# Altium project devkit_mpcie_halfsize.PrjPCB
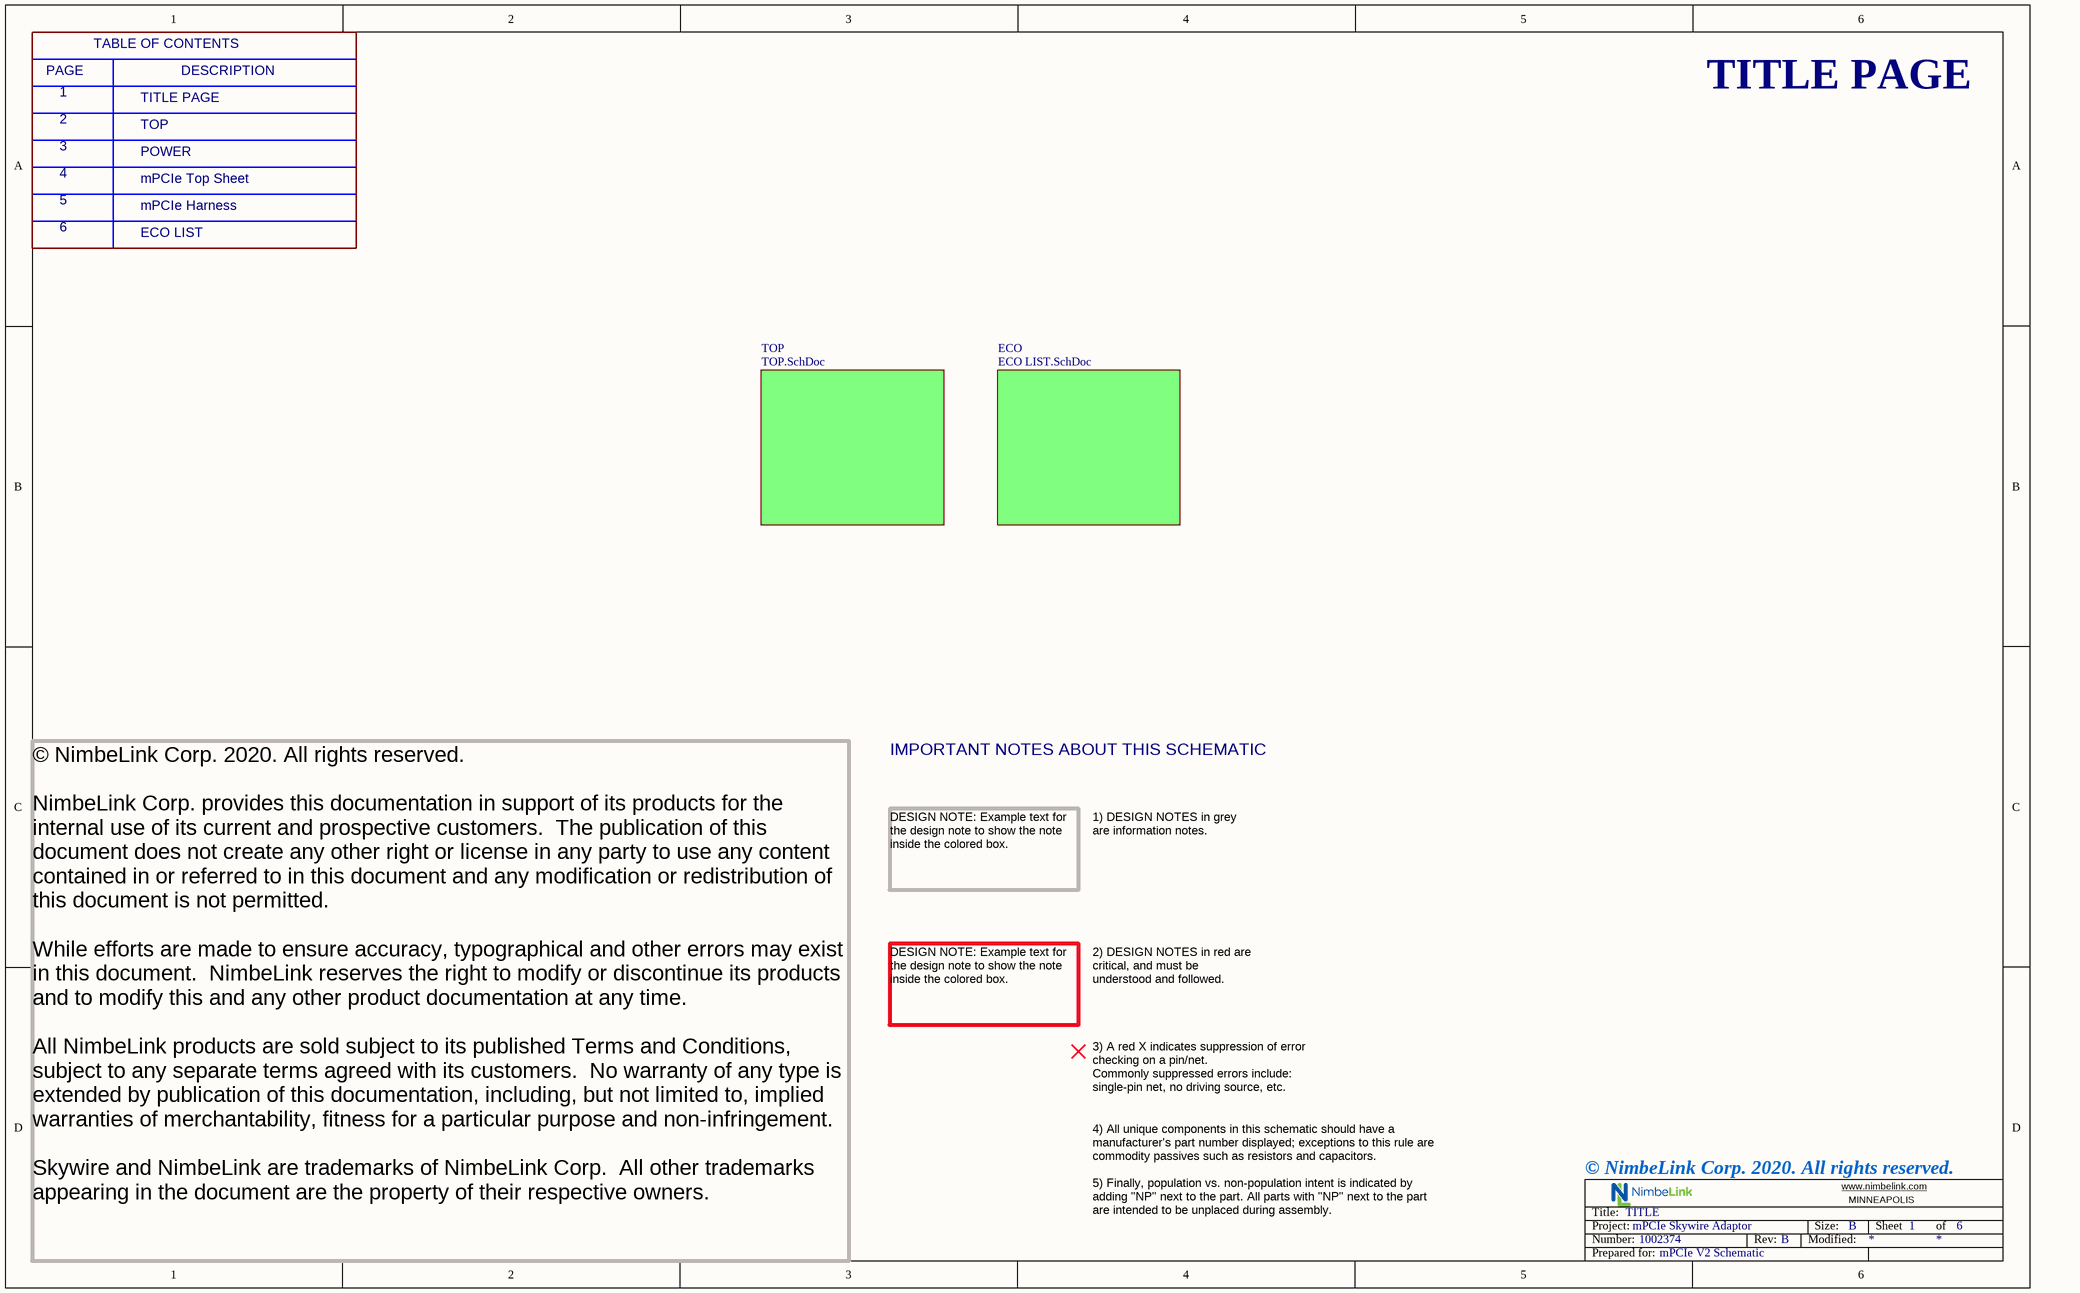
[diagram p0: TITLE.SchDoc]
Template Source URL: http://www.pcisig.com/members/downloads/specifications/pciexpress/PCI_Express_Mini_CEM_12_26Oct07_ncb.pdf; Template Source Revision Date: rev 1.2, Oct 26, 2007; Template Source Organization: Nimbelink; Template Source Name: PCI Express Mini CEM 1.2; Template Family: PCI Express; ProjectTitle: Skywire mPCIe V2 half card; ProjectOrganization: Nimbelink, Corp; NL_VERBOSE_CUST_NAME: mPCIe V2 Schematic; NL_SCH_REV: B; NL_SCH_PN: 1002374; NL_PCBA_REV: B; NL_PCBA_PN: 1002373; NL_PCB_REV: A; NL_PCB_PN: 1002580; NL_BILLING_CODE: mPCIe Skywire Adaptor
6 sheets, 85 parts. Net scope: flat (ports and power ports of the same name join across sheets).
Board file: devkit_mpcie_halfsize.PcbDoc
Sheets:
  TITLE.SchDoc
    TOP = TOP.SchDoc
      Designator = PCI Express Mini_3000X2680_52PIN_Half-Mini-Type H2.schdoc
        U_CON_PCI Express Mini_P1_52PIN = CON_PCI Express Mini_P1_52PIN.SchDoc
      Power = Power.SchDoc
    ECO = ECO LIST.SchDoc

## Sheet TITLE.SchDoc: TITLE
size B; DocumentNumber: 1; SheetNumber: 1; SheetTotal: 6

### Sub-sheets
ECO = ECO LIST.SchDoc: no entries
TOP = TOP.SchDoc: no entries

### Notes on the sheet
- PAGE
- 1
- TABLE OF CONTENTS
- TITLE PAGE
- DESCRIPTION
- 2
- 3
- TOP
- POWER
- 4
- 5
- 6
- mPCIe Top Sheet
- ECO LIST
- mPCIe Harness
- IMPORTANT NOTES ABOUT THIS SCHEMATIC
- DESIGN NOTE: Example text for the design note to show the note inside the colored box.
- 1) DESIGN NOTES in grey are information notes.
- 2) DESIGN NOTES in red are critical, and must be understood and followed.
- 3) A red X indicates suppression of error checking on a pin/net.
  Commonly suppressed errors include: single-pin net, no driving source, etc.
- © NimbeLink Corp. 2020. All rights reserved.
- 4) All unique components in this schematic should have a manufacturer's part number displayed; exceptions to this rule are commodity passives such as resistors and capacitors.
  5) Finally, population vs. non-population intent is indicated by adding "NP" next to the part. All parts with "NP" next to the part are intended to be unplaced during assembly.
- © NimbeLink Corp. 2020. All rights reserved.
  NimbeLink Corp. provides this documentation in support of its products for the internal use of its current and prospective customers.  The publication of this document does not create any other right or license in any party to use any content contained in or referred to in this document and any modification or redistribution of this document is not permitted.
  While efforts are made to ensure accuracy, typographical and other errors may exist in this document.  NimbeLink reserves the right to modify or discontinue its products and to modify this and any other product documentation at any time.
  All NimbeLink products are sold subject to its published Terms and Conditions, subject to any separate terms agreed with its customers.  No warranty of any type is extended by publication of this documentation, including, but not limited to, implied warranties of merchantability, fitness for a particular purpose and non-infringement.
  Skywire and NimbeLink are trademarks of NimbeLink Corp.  All other trademarks appearing in the document are the property of their respective owners.

## Sheet TOP.SchDoc: TOP
size B; DocumentNumber: 2; SheetNumber: 2; SheetTotal: 6
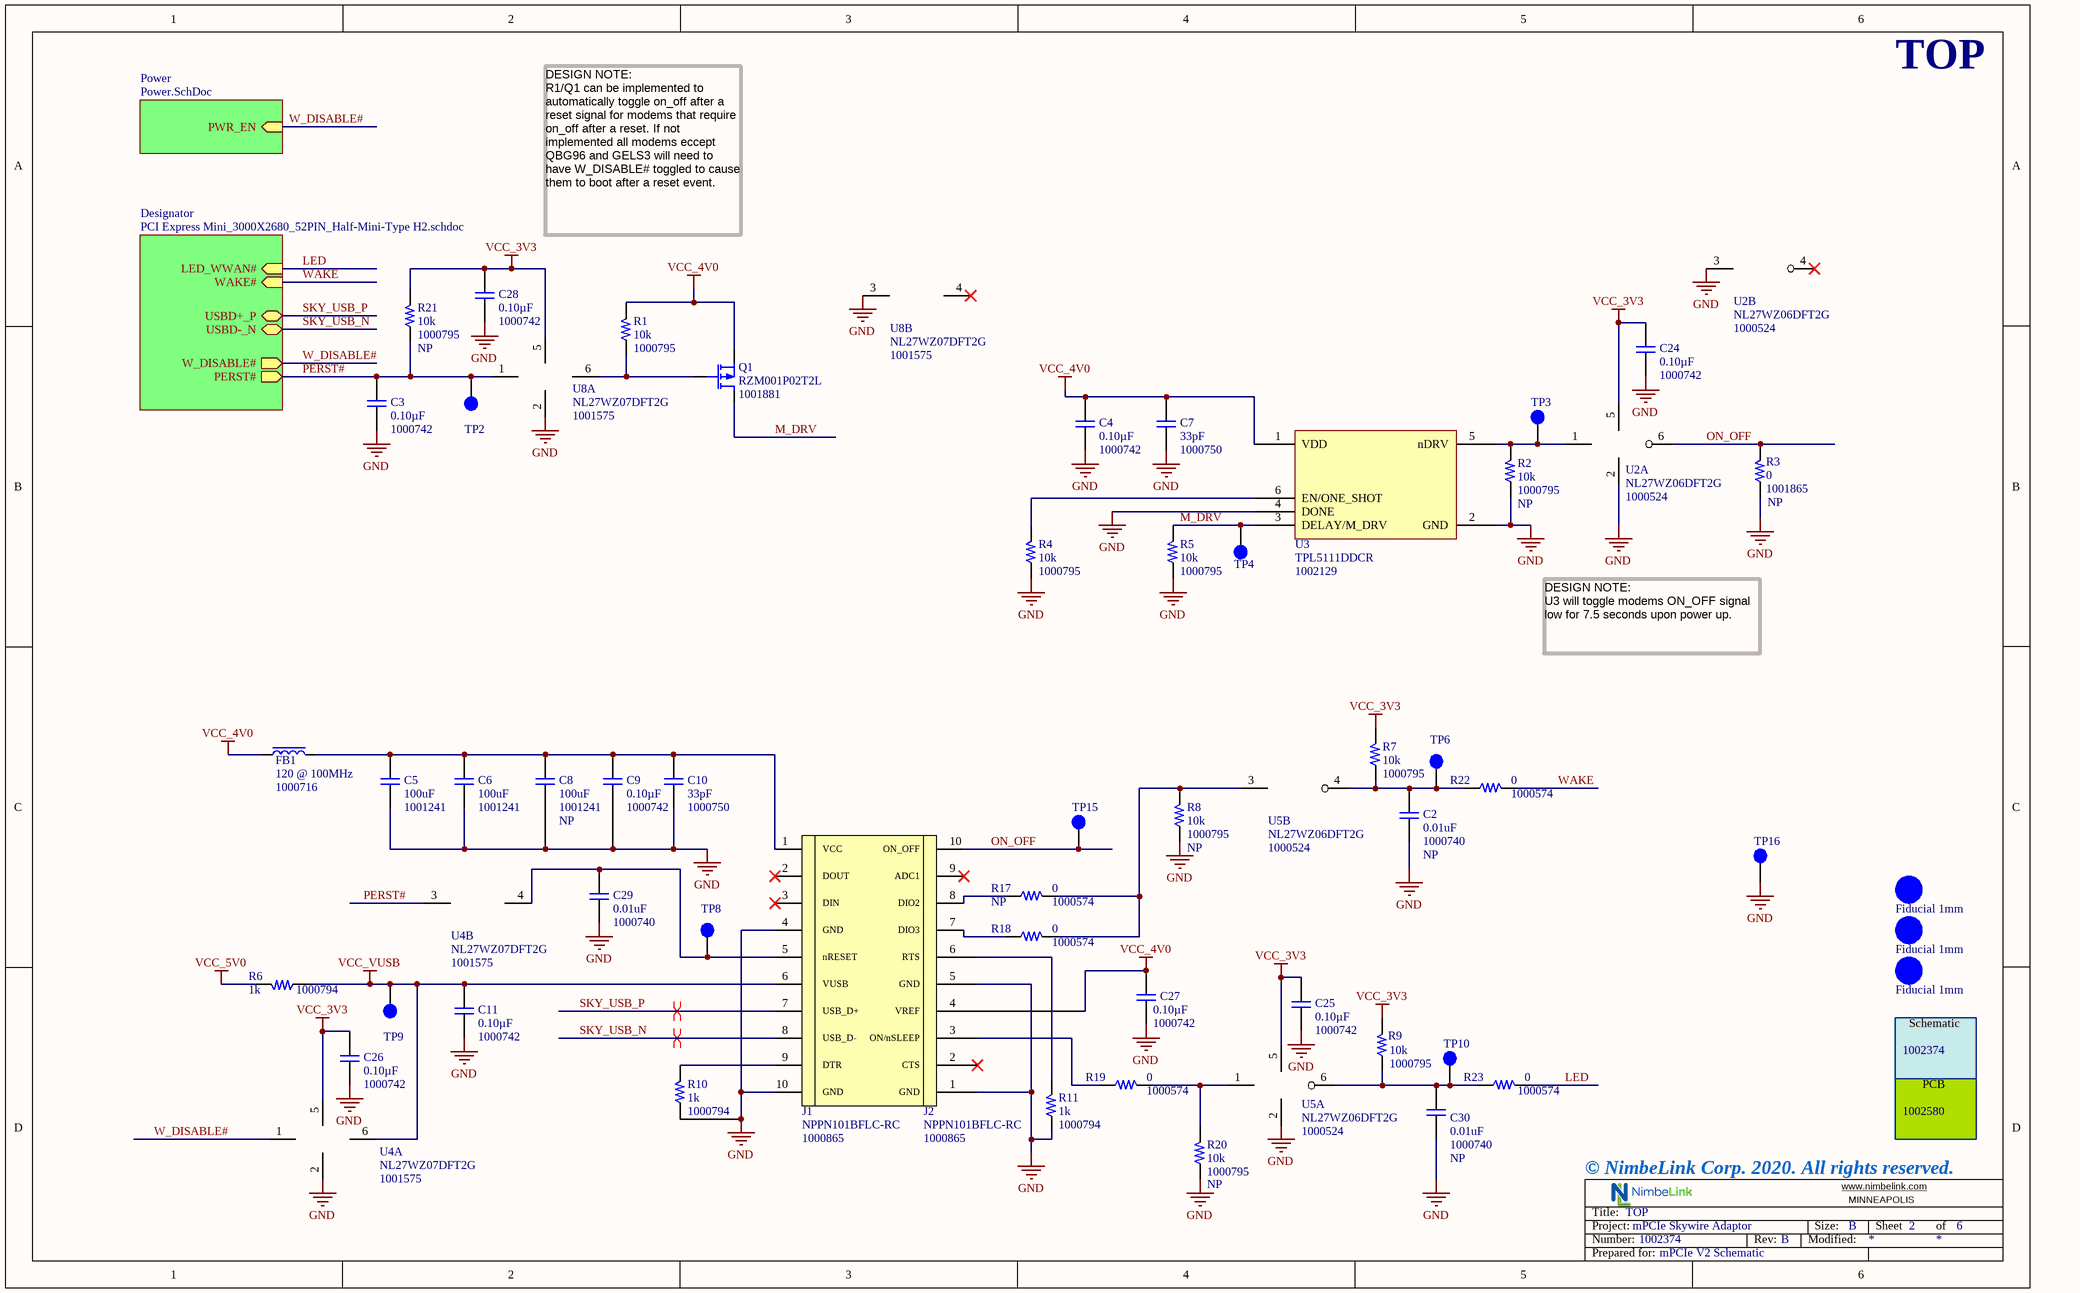
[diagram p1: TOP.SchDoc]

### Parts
C2  Population: NP  Part_Number: 1000740  Capacitance: 0.01uF  [0402]  (hidden comment: CAPACITOR)
C3  Capacitance: 0.10µF  Part_Number: 1000742  [0402]
C4  Capacitance: 0.10µF  Part_Number: 1000742  [0402]
C5  Capacitance: 100uF  [CAPC3225X25N_1210]  (hidden comment: 1001241)
C6  Capacitance: 100uF  [CAPC3225X25N_1210]  (hidden comment: 1001241)
C7  Part_Number: 1000750  Capacitance: 33pF  [0402]  (hidden comment: C, 33 pF, 50V, 5%, C0G/NP0, 0402 CER)
C8  Population: NP  Capacitance: 100uF  [CAPC3225X25N_1210]  (hidden comment: 1001241)
C9  Capacitance: 0.10µF  Part_Number: 1000742  [0402]
C10  Part_Number: 1000750  Capacitance: 33pF  [0402]  (hidden comment: C, 33 pF, 50V, 5%, C0G/NP0, 0402 CER)
C11  Capacitance: 0.10µF  Part_Number: 1000742  [0402]
C24  Capacitance: 0.10µF  Part_Number: 1000742  [0402]
C25  Capacitance: 0.10µF  Part_Number: 1000742  [0402]
C26  Capacitance: 0.10µF  Part_Number: 1000742  [0402]
C27  Capacitance: 0.10µF  Part_Number: 1000742  [0402]
C28  Capacitance: 0.10µF  Part_Number: 1000742  [0402]
C29  Part_Number: 1000740  Capacitance: 0.01uF  [0402]  (hidden comment: CAPACITOR)
C30  Population: NP  Part_Number: 1000740  Capacitance: 0.01uF  [0402]  (hidden comment: CAPACITOR)
FB1  Part_Number: 1000716  Resistance_at_Frequency: 120 @ 100MHz  [0603]  (hidden comment: PE-0603PFB121ST)
Fiducial1  Fiducial 1mm  [Fiducial 1mm]  (no BOM)
Fiducial2  Fiducial 1mm  [Fiducial 1mm]  (no BOM)
Fiducial3  Fiducial 1mm  [Fiducial 1mm]  (no BOM)
J1  1000865  [NPPN101BFLC-RC]
J2  1000865  [NPPN101BFLC-RC]
PCB1  Part_Number: 1002580  (hidden comment: PCB)  (mechanical)
Q1  Manufacturer_Part_Number1: RZM001P02T2L  Part_Number: 1001881  [SOT-723]  (hidden comment: MOSFET_P)
R1  Part_Number: 1000795  Resistance_Ohms: 10k  [0402]  (hidden comment: R, 10K, 1%, 1/16W,  0402)
R2  Population: NP  Part_Number: 1000795  Resistance_Ohms: 10k  [0402]  (hidden comment: R, 10K, 1%, 1/16W,  0402)
R3  Population: NP  Resistance_Ohms: 0  Part_Number: 1001865  [0402]  (hidden comment: RESISTOR)
R4  Part_Number: 1000795  Resistance_Ohms: 10k  [0402]  (hidden comment: R, 10K, 1%, 1/16W,  0402)
R5  Part_Number: 1000795  Resistance_Ohms: 10k  [0402]  (hidden comment: R, 10K, 1%, 1/16W,  0402)
R6  Part_Number: 1000794  Resistance_Ohms: 1k  [0402]  (hidden comment: R, 1K, 1%, 1/16W, 0402)
R7  Part_Number: 1000795  Resistance_Ohms: 10k  [0402]  (hidden comment: R, 10K, 1%, 1/16W,  0402)
R8  Population: NP  Part_Number: 1000795  Resistance_Ohms: 10k  [0402]  (hidden comment: R, 10K, 1%, 1/16W,  0402)
R9  Part_Number: 1000795  Resistance_Ohms: 10k  [0402]  (hidden comment: R, 10K, 1%, 1/16W,  0402)
R10  Part_Number: 1000794  Resistance_Ohms: 1k  [0402]  (hidden comment: R, 1K, 1%, 1/16W, 0402)
R11  Part_Number: 1000794  Resistance_Ohms: 1k  [0402]  (hidden comment: R, 1K, 1%, 1/16W, 0402)
R17  Population: NP  Part_Number: 1000574  [0402]  (hidden comment: 0)
R18  Part_Number: 1000574  [0402]  (hidden comment: 0)
R19  Part_Number: 1000574  [0402]  (hidden comment: 0)
R20  Population: NP  Part_Number: 1000795  Resistance_Ohms: 10k  [0402]  (hidden comment: R, 10K, 1%, 1/16W,  0402)
R21  Population: NP  Part_Number: 1000795  Resistance_Ohms: 10k  [0402]  (hidden comment: R, 10K, 1%, 1/16W,  0402)
R22  Part_Number: 1000574  [0402]  (hidden comment: 0)
R23  Part_Number: 1000574  [0402]  (hidden comment: 0)
SCH1  Part_Number: 1002374  (hidden comment: SCH)  (mechanical)
TP2  Test Point 1mm  [Test_Point 1mm]  (value not drawn)  (no BOM)
TP3  Test Point 1mm  [Test_Point 1mm]  (value not drawn)  (no BOM)
TP4  Test Point 1mm  [Test_Point 1mm]  (value not drawn)  (no BOM)
TP6  Test Point 1mm  [Test_Point 1mm]  (value not drawn)  (no BOM)
TP8  Test Point 1mm  [Test_Point 1mm]  (value not drawn)  (no BOM)
TP9  Test Point 1mm  [Test_Point 1mm]  (value not drawn)  (no BOM)
TP10  Test Point 1mm  [Test_Point 1mm]  (value not drawn)  (no BOM)
TP15  Test Point 1mm  [Test_Point 1mm]  (value not drawn)  (no BOM)
TP16  Test Point 1mm  [Test_Point 1mm]  (value not drawn)  (no BOM)
U2  Part_Number: 1000524  [SOT65P210X110-6N]  (hidden comment: NL27WZ06DFT2G)  (parts A,B of 2)
U3  Manufacturer_Part_Number1: TPL5111DDCR  Part_Number: 1002129  [SOT95P280X110-6N]  (hidden comment: TPL5111)
U4  Part_Number: 1001575  [SOT65P210X110-6N]  (hidden comment: NL27WZ07DFT2G)  (parts A,B of 2)
U5  Part_Number: 1000524  [SOT65P210X110-6N]  (hidden comment: NL27WZ06DFT2G)  (parts A,B of 2)
U8  Part_Number: 1001575  [SOT65P210X110-6N]  (hidden comment: NL27WZ07DFT2G)  (parts A,B of 2)

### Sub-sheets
Designator = PCI Express Mini_3000X2680_52PIN_Half-Mini-Type H2.schdoc: USBD+_P (bidir), USBD-_N (bidir), PERST# (out), WAKE# (in), LED_WWAN# (in), W_DISABLE# (out)
Power = Power.SchDoc: PWR_EN (in)

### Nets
GND: C2.2 C3.2 C4.2 C5.2 C6.2 C7.2 C8.2 C9.2 C10.2 C11.2 C24.2 C25.2 C26.2 C27.2 C28.2 C29.2 C30.2 J1.4 J1.10 J2.1 J2.5 R2.1 R3.1 R4.1 R5.1 R8.1 R10.1 R11.1 R20.1 TP16.1 U2.2(GND) U2.3 U3.2(GND) U3.4(DONE) U4.2(GND) U5.2(GND) U8.2(GND) U8.3
VCC_3V3: C24.1 C25.1 C26.1 C28.1 R7.2 R9.2 R21.2 U2.5(VCC) U4.5(VCC) U5.5(VCC) U8.5(VCC)
VCC_4V0: C4.1 C7.1 C27.1 FB1.1 J2.4 Q1.2(S) R1.2 U3.1(VDD)
VCC_5V0: R6.2
VCC_VUSB: C11.1 J1.6 R6.1 TP9.1 U4.6
LED: R23.2 ; sheet Designator/LED_WWAN#
M_DRV: Q1.3(D) R5.2 TP4.1 U3.3(DELAY/M_DRV)
ON_OFF: J2.10 R3.2 TP15.1 U2.6
PERST#: C3.1 R21.1 TP2.1 U4.3 U8.1 ; sheet Designator/PERST#
SKY_USB_N: J1.8 ; sheet Designator/USBD-_N
SKY_USB_P: J1.7 ; sheet Designator/USBD+_P
W_DISABLE#: U4.1 ; sheet Designator/W_DISABLE#, sheet Power/PWR_EN
WAKE: R22.2 ; sheet Designator/WAKE#
NetC2_1: C2.1 R7.1 R22.1 TP6.1 U5.4
NetC5_1: C5.1 C6.1 C8.1 C9.1 C10.1 FB1.2 J1.1
NetC29_1: C29.1 J1.5 TP8.1 U4.4
NetC30_1: C30.1 R9.1 R23.1 TP10.1 U5.6
NetJ1_9: J1.9 R10.2
NetJ2_3: J2.3 R19.1
NetJ2_6: J2.6 R11.2
NetJ2_7: J2.7 R18.1
NetJ2_8: J2.8 R17.1
NetQ1_1: Q1.1(G) R1.1 U8.6
NetR2_2: R2.2 TP3.1 U2.1 U3.5(nDRV)
NetR4_2: R4.2 U3.6(EN/ONE_SHOT)
NetR8_2: R8.2 R17.2 R18.2 U5.3
NetR19_2: R19.2 R20.2 U5.1

Not connected (* = marked no-connect by the designer): J1 2* 3*; J2 2* 9*; U2 4*; U8 4*

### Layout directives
differential pair: SKY_USB_N, SKY_USB_P

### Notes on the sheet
- TOP
- DESIGN NOTE:
  R1/Q1 can be implemented to automatically toggle on_off after a reset signal for modems that require on_off after a reset. If not implemented all modems eccept QBG96 and GELS3 will need to have W_DISABLE# toggled to cause them to boot after a reset event.
- DESIGN NOTE:
  U3 will toggle modems ON_OFF signal low for 7.5 seconds upon power up.
- (near J1) VCC
- (near J1) DOUT
- (near J1) DIN
- (near J2) ON_OFF
- (near J2) ADC1
- (near J2) DIO2
- (near J1) GND
- (near J1) nRESET
- (near J2) DIO3
- (near J2) RTS
- (near J1) VUSB
- (near J1) USB_D+
- (near J1) USB_D-
- (near J2) ON/nSLEEP
- (near J2) VREF
- (near J2) GND
- (near J1) DTR
- (near J2) CTS
- (near PCB1) © NimbeLink Corp. 2020. All rights reserved.

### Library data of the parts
C2 C29 C30 = 1000740: Capacitor, 0.01 uF, 25V, 5%, X7R, 0402
C3 C4 C9 C11 C24-C28 = 1000742: Capacitor, 0.1 uF, 16V, 10%, X7R, 0402; Manufacturer1: Kemet; Manufacturer_Part_Number1: C0402C104K4RALTU; Item_Phase: Production; Capacitor_Type: Ceramic; Mounting_Type: Surface Mount; Operating_Temperature: -55°C ~ 125°C; Thickness_Max: 0.022" (0.55mm)
C5 C6 C8 = 1001241: Capacitor. 100uF, 10V, 20%, X5R, 1210; Manufacturer1: Taiyo Yuden; Tolerance: +/- 20%; Item_Phase: Production; Capacitor_Type: Ceramic; Mounting_Type: Surface Mount; Operating_Temperature: -55C ~ +85C; Thickness_Max: 0.106 (2.70mm)"
C7 C10 = 1000750: Capacitor, 33 pF, 50V, 5%, C0G/NP0, 0402; Manufacturer1: Kemet; Manufacturer_Part_Number1: C0402C330J5GACTU; Item_Phase: Production; Capacitor_Type: Ceramic; Mounting_Type: Surface Mount; Operating_Temperature: -55°C ~ 125°C; Temperature_Coefficient: C0G, NP0; Thickness_Max: 0.022" (0.55mm)
FB1 = 1000716: Ferrite Bead, 120 ohm @100mHz, 2A, 50mOHM-DC, 0603; Manufacturer_Part_Number1: BLM18PG121SZ1D; Manufacturer1: Murata Electronics North America; Item_Phase: Production; Mounting_Type: Surface Mount; Resistance_DC: 50 mOhm
Fiducial1-Fiducial3 = Fiducial: Population: NP
J1 J2 = 1000865: Connector, Female, 2.00mm, 10x1, SMD, Left Oriented; Manufacturer1: Sullins Connector Solutions; Item_Phase: Production; Connector_Type: Header; Contact_Finish: Gold; Contact_Type: Female Socket; Current_Rating: 2A; Fastening_Type: Push-Pull; Header_Orientation: Vertical; Insertion_Removal_Method: Push In / Pull Out; Mounting_Type: Surface Mount; Number_of_Pins: 10; Number_of_Rows: 1; Operating_Temperature: -40°C ~ 105°C; Pitch: 0.079" (2.00mm); Voltage_Rating: 150V
PCB1 = PCB: PCB Part Number
Q1 = 1001881: Transistor, MOSFET, P-CH, 20V, 0.100A, SOT-723; Manufacturer1: Rohm Semiconductor; Item_Phase: Production; Mounting_Type: Surface Mount; Operating_Temperature: -55°C ~ 150°C; Transistor_Type: PCH - FET
R1 R2 R4 R5 R7-R9 R20 R21 = 1000795: Resistor, 10K, 1%, 1/16W, 0402; Manufacturer1: Bourns Inc; Manufacturer_Part_Number1: CR0402-FX-1002GLF; Item_Phase: Production; Mounting_Type: Surface Mount; Number_of_Terminations: 2; Operating_Temperature: -55°C ~ 155°C; Power: 0.063W, 1/16W; Resistor_Package: 0402 (1005 Metric); Temperature_Coefficient: ±100ppm/°C
R3 = 1001865: Resistor, 0, 1/16W, 0402; Manufacturer1: Bourns Inc; Manufacturer_Part_Number1: CR0402-J/-000GLF; Item_Phase: Production; Mounting_Type: Surface Mount; Number_of_Terminations: 2; Operating_Temperature: -55C ~ 155C; Resistor_Package: 0402 (1005 Metric)
R6 R10 R11 = 1000794: Resistor, 1K, 1%, 1/16W, 0402; Manufacturer1: Bourns Inc; Manufacturer_Part_Number1: CR0402-FX-1001GLF; Item_Phase: Production; Mounting_Type: Surface Mount; Number_of_Terminations: 2; Operating_Temperature: -55°C ~ 155°C; Power: 0.063W, 1/16W; Resistor_Package: 0402 (1005 Metric); Temperature_Coefficient: ±100ppm/°C
R17-R19 R22 R23 = 1000574: Resistor, 0, 1/10W, 0402; Manufacturer1: Panasonic Electronic Components; Manufacturer_Part_Number1: ERJ-2GE0R00X; Item_Phase: Production; Mounting_Type: Surface Mount; Number_of_Terminations: 2; Operating_Temperature: -55°C ~ 155°C; Power: 0.1W, 1/10W; Resistor_Package: 0402 (1005 Metric); Tolerance: Jumper
SCH1 = SCH: Schematic Part Number
TP2-TP4 TP6 TP8-TP10 TP15 TP16 = TP_1mm: TEST POINT, SMD 1mm; Population: NP
U2 U5 = 1000524: IC, Inverter, Dual, Open Drain,1.65-5.5V, SC88; Manufacturer1: ON Semiconductor; Item_Phase: Production; Mounting_Type: Surface Mount; Operating_Temperature: -55°C ~ 125°C; Voltage_Supply_Max: 5.5V; Voltage_Supply_Min: 1.65V
U3 = 1002129: IC, Timer, 0.1-7200s, 1%, 1.8V-5.5V, TSOT-23-6; Manufacturer1: Texas Instruments; Item_Phase: Production; IC_Function: Logic; Mounting_Type: Surface Mount; Operating_Temperature: -40C to +105C; Voltage_Supply_Max: 5.5V; Voltage_Supply_Min: 1.8V; Voltage_Supply_Typical: 3.3V
U4 U8 = 1001575: IC, Buffer, Dual, Open Drain,1.65-5.5V, SC88; Manufacturer1: ON Semiconductor; Item_Phase: Preliminary; IC_Function: Logic; Mounting_Type: Surface Mount; Operating_Temperature: -55°C ~ 125°C; Voltage_Supply_Max: 5.5V; Voltage_Supply_Min: 1.65V

## Sheet PCI Express Mini_3000X2680_52PIN_Half-Mini-Type H2.schdoc: PCI Express H2 Top Sheet
size B; DocumentNumber: 4; Revision: 3; SheetNumber: 4; SheetTotal: 6; Item: 20027; ItemRevision: 3
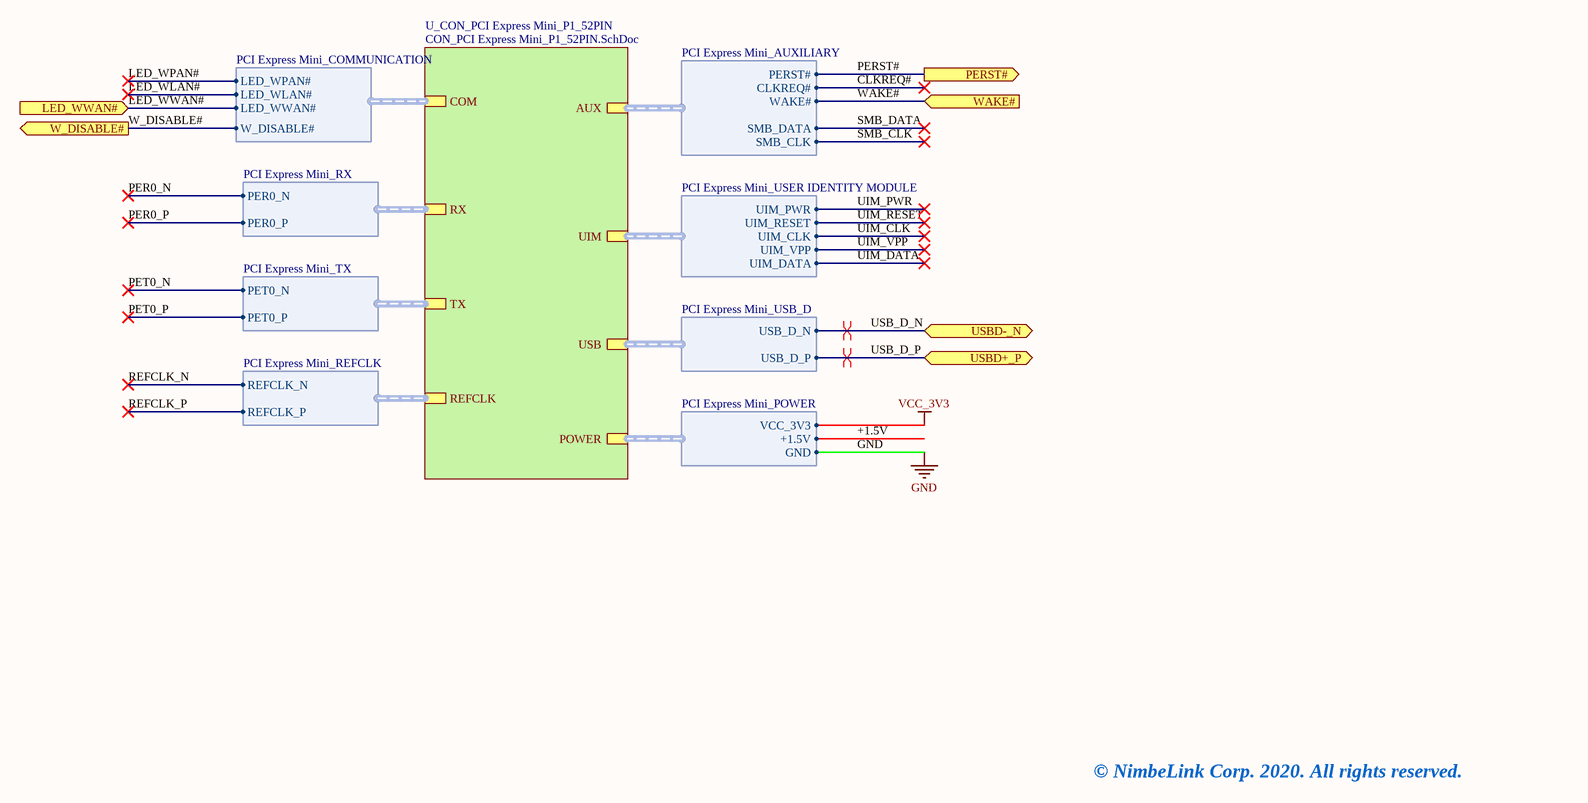
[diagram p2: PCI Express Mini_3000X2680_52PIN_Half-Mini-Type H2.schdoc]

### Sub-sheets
U_CON_PCI Express Mini_P1_52PIN = CON_PCI Express Mini_P1_52PIN.SchDoc: POWER (harness PCI Express Mini_POWER), COM (harness PCI Express Mini_COMMUNICATION), USB (harness PCI Express Mini_USB_D), AUX (harness PCI Express Mini_AUXILIARY), UIM (harness PCI Express Mini_USER IDENTITY MODULE), RX (harness PCI Express Mini_RX), TX (harness PCI Express Mini_TX), REFCLK (harness PCI Express Mini_REFCLK)

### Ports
LED_WWAN# (in), PERST# (out), USBD+_P (bidir), USBD-_N (bidir), W_DISABLE# (out), WAKE# (in)

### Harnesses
PCI Express Mini_USB_D: USB_D_N, USB_D_P
PCI Express Mini_POWER: VCC_3V3, +1.5V, GND
PCI Express Mini_AUXILIARY: PERST#, CLKREQ#, WAKE#, SMB_DATA, SMB_CLK
PCI Express Mini_COMMUNICATION: LED_WPAN#, LED_WLAN#, LED_WWAN#, W_DISABLE#
PCI Express Mini_USER IDENTITY MODULE: UIM_PWR, UIM_RESET, UIM_CLK, UIM_VPP, UIM_DATA
PCI Express Mini_REFCLK: REFCLK_N, REFCLK_P
PCI Express Mini_RX: PER0_N, PER0_P
PCI Express Mini_TX: PET0_N, PET0_P

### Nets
LED_WWAN#: port LED_WWAN#, sheet U_CON_PCI Express Mini_P1_52PIN/COM.LED_WWAN#
PERST#: port PERST#, sheet U_CON_PCI Express Mini_P1_52PIN/AUX.PERST#
USB_D_N: port USBD-_N, sheet U_CON_PCI Express Mini_P1_52PIN/USB.USB_D_N
USB_D_P: port USBD+_P, sheet U_CON_PCI Express Mini_P1_52PIN/USB.USB_D_P
W_DISABLE#: port W_DISABLE#, sheet U_CON_PCI Express Mini_P1_52PIN/COM.W_DISABLE#
WAKE#: port WAKE#, sheet U_CON_PCI Express Mini_P1_52PIN/AUX.WAKE#

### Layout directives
differential pair: USB_D_N, USB_D_P

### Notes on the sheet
- © NimbeLink Corp. 2020. All rights reserved.

## Sheet CON_PCI Express Mini_P1_52PIN.SchDoc: PCI Express Mini 52Pin
size B; DocumentNumber: 5; SheetNumber: 5; SheetTotal: 6
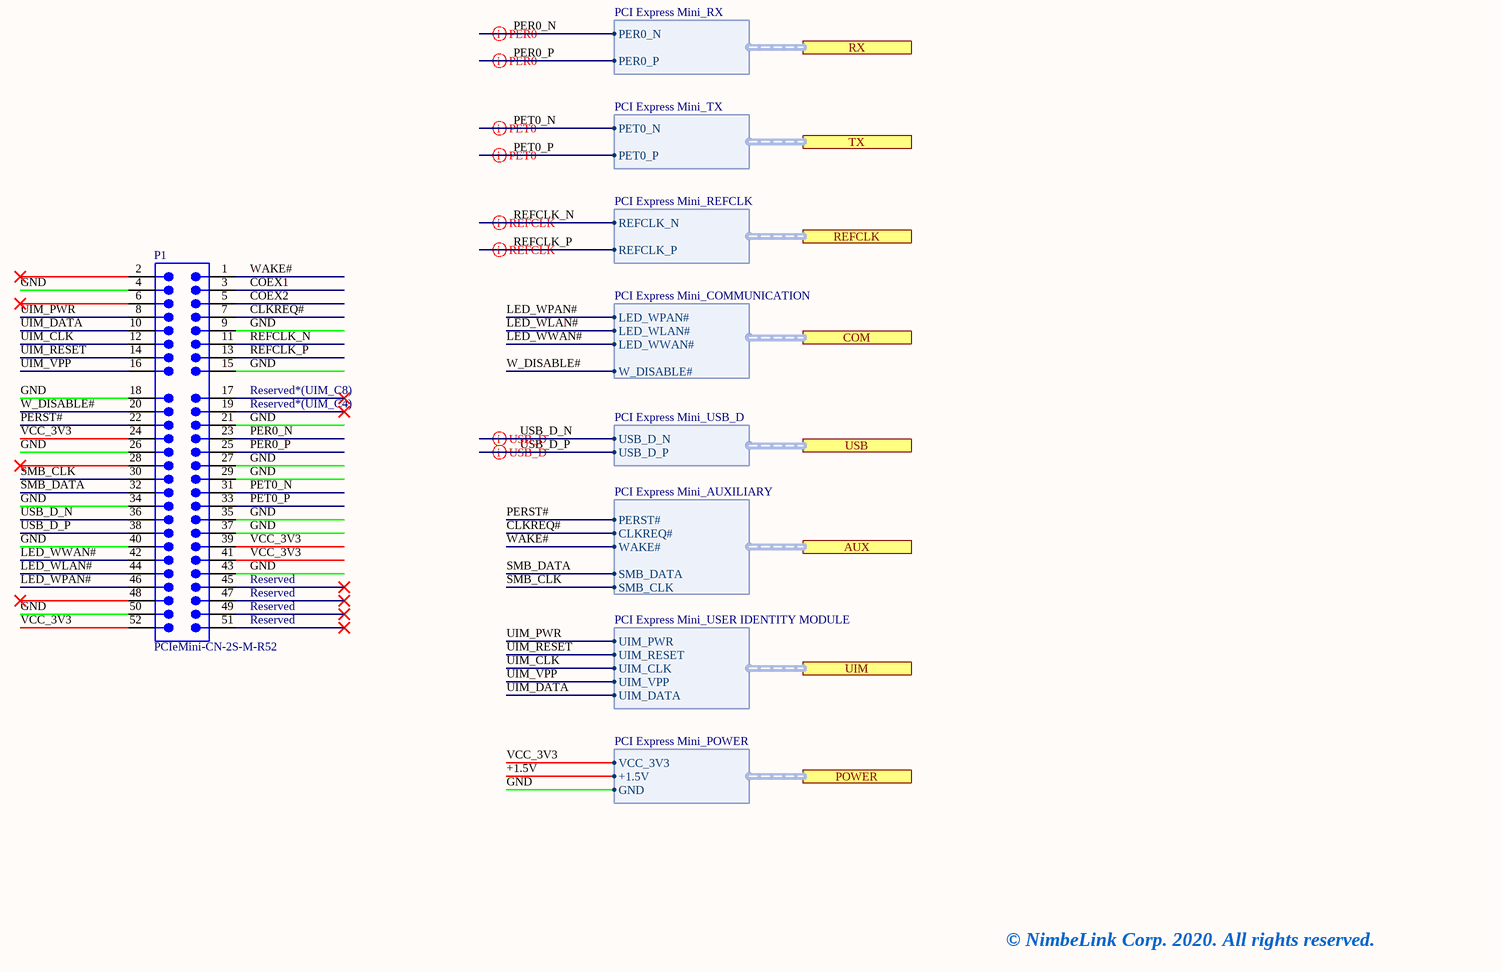
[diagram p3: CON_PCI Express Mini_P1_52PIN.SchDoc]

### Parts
P1  PCIeMini-CN-2S-M-R52  [PCIeMini-GF-2D-800-1K-S52]  (no BOM)

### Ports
AUX (harness PCI Express Mini_AUXILIARY), COM (harness PCI Express Mini_COMMUNICATION), POWER (harness PCI Express Mini_POWER), REFCLK (harness PCI Express Mini_REFCLK), RX (harness PCI Express Mini_RX), TX (harness PCI Express Mini_TX), UIM (harness PCI Express Mini_USER IDENTITY MODULE), USB (harness PCI Express Mini_USB_D)

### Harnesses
PCI Express Mini_REFCLK: REFCLK_N, REFCLK_P
PCI Express Mini_RX: PER0_N, PER0_P
PCI Express Mini_TX: PET0_N, PET0_P
PCI Express Mini_USB_D: USB_D_N, USB_D_P
PCI Express Mini_POWER: VCC_3V3, +1.5V, GND
PCI Express Mini_AUXILIARY: PERST#, CLKREQ#, WAKE#, SMB_DATA, SMB_CLK
PCI Express Mini_COMMUNICATION: LED_WPAN#, LED_WLAN#, LED_WWAN#, W_DISABLE#
PCI Express Mini_USER IDENTITY MODULE: UIM_PWR, UIM_RESET, UIM_CLK, UIM_VPP, UIM_DATA

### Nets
CLKREQ#: P1.7 ; port AUX.CLKREQ#
COEX1: P1.3
COEX2: P1.5
GND: P1.4 P1.9 P1.15 P1.18 P1.21 P1.26 P1.27 P1.29 P1.34 P1.35 P1.37 P1.40 P1.43 P1.50 ; port POWER.GND
LED_WLAN#: P1.44 ; port COM.LED_WLAN#
LED_WPAN#: P1.46 ; port COM.LED_WPAN#
LED_WWAN#: P1.42 ; port COM.LED_WWAN#
PER0_N: P1.23 ; port RX.PER0_N
PER0_P: P1.25 ; port RX.PER0_P
PERST#: P1.22 ; port AUX.PERST#
PET0_N: P1.31 ; port TX.PET0_N
PET0_P: P1.33 ; port TX.PET0_P
REFCLK_N: P1.11 ; port REFCLK.REFCLK_N
REFCLK_P: P1.13 ; port REFCLK.REFCLK_P
SMB_CLK: P1.30 ; port AUX.SMB_CLK
SMB_DATA: P1.32 ; port AUX.SMB_DATA
UIM_CLK: P1.12 ; port UIM.UIM_CLK
UIM_DATA: P1.10 ; port UIM.UIM_DATA
UIM_PWR: P1.8 ; port UIM.UIM_PWR
UIM_RESET: P1.14 ; port UIM.UIM_RESET
UIM_VPP: P1.16 ; port UIM.UIM_VPP
USB_D_N: P1.36 ; port USB.USB_D_N
USB_D_P: P1.38 ; port USB.USB_D_P
VCC_3V3: P1.24 P1.39 P1.41 P1.52 ; port POWER.VCC_3V3
W_DISABLE#: P1.20 ; port COM.W_DISABLE#
WAKE#: P1.1 ; port AUX.WAKE#

Not connected (* = marked no-connect by the designer): P1 2* 6* 17* 19* 28* 45* 47* 48* 49* 51*

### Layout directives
differential pair: PER0_N, PER0_P, PET0_N, PET0_P, REFCLK_N, REFCLK_P, USB_D_N, USB_D_P

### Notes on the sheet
- (near P1) Reserved*(UIM_C8)
- (near P1) Reserved*(UIM_C4)
- (near P1) Reserved
- © NimbeLink Corp. 2020. All rights reserved.

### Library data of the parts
P1 = CMP-0001-00067-2: Golden finger, PCIeMini, Dual, Staggered, Pitch 0.8mm, 52-Position; Mating Connector: Tyco-292443-1; Package Version: rev1.2, Oct-2007

## Sheet Power.SchDoc: TOP
size B; DocumentNumber: 3; SheetNumber: 3; SheetTotal: 6
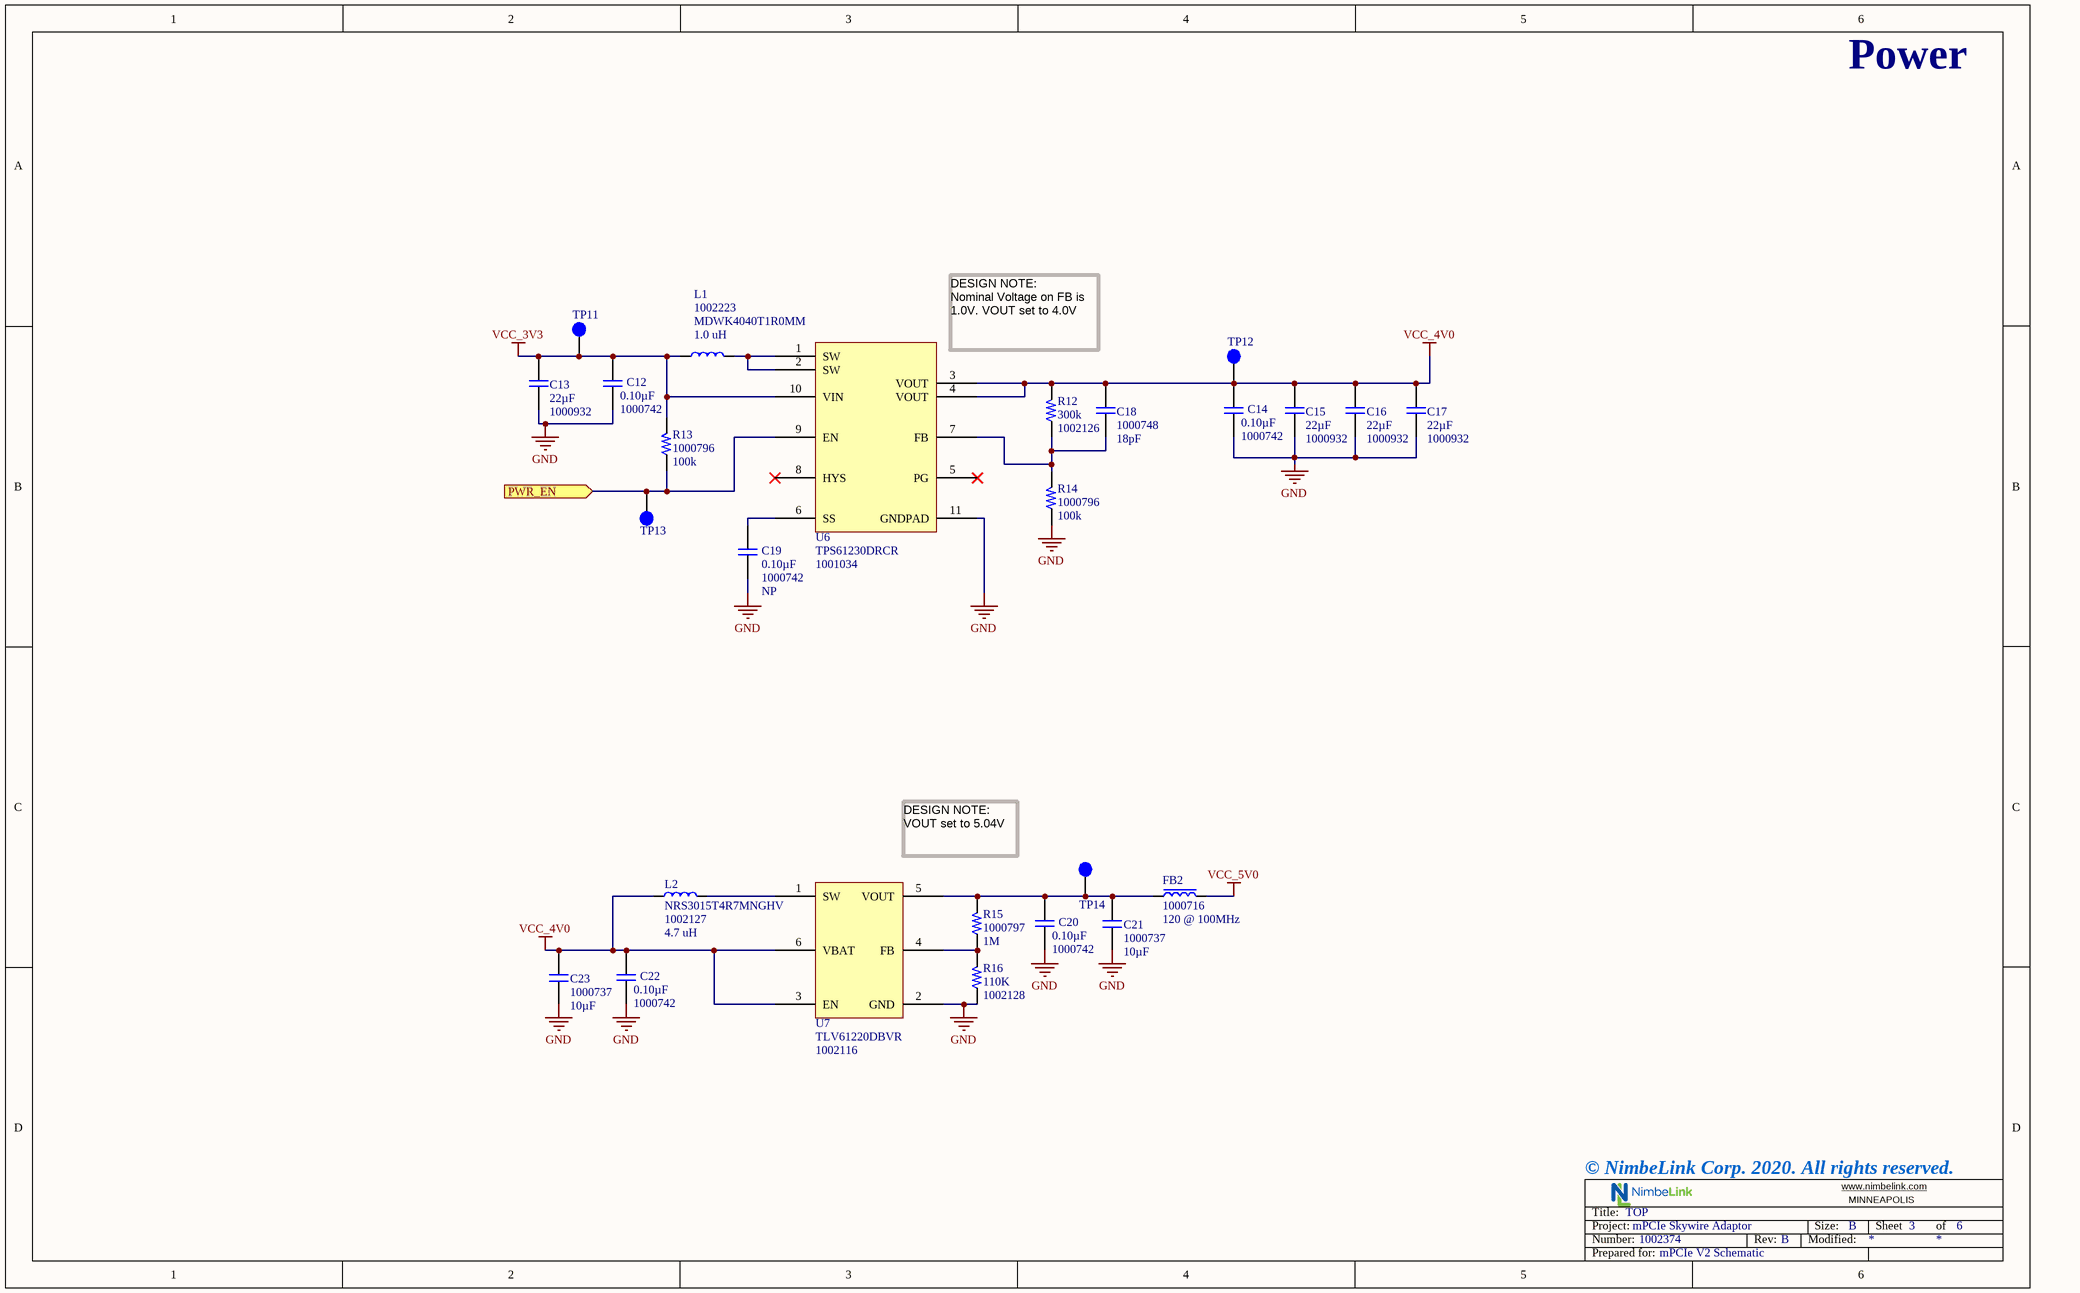
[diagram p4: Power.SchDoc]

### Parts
C12  Capacitance: 0.10µF  Part_Number: 1000742  [0402]
C13  Capacitance: 22µF  Part_Number: 1000932  [0603]
C14  Capacitance: 0.10µF  Part_Number: 1000742  [0402]
C15  Capacitance: 22µF  Part_Number: 1000932  [0603]
C16  Capacitance: 22µF  Part_Number: 1000932  [0603]
C17  Capacitance: 22µF  Part_Number: 1000932  [0603]
C18  Part_Number: 1000748  Capacitance: 18pF  [0402]  (hidden comment: C, 18 pF, 50V, 5%, C0G/NPO, 0402 CER)
C19  Population: NP  Capacitance: 0.10µF  Part_Number: 1000742  [0402]
C20  Capacitance: 0.10µF  Part_Number: 1000742  [0402]
C21  Part_Number: 1000737  Capacitance: 10µF  [0402]  (hidden comment: C, 10 uF, 10V, X5R, 20%, 0402 CER)
C22  Capacitance: 0.10µF  Part_Number: 1000742  [0402]
C23  Part_Number: 1000737  Capacitance: 10µF  [0402]  (hidden comment: C, 10 uF, 10V, X5R, 20%, 0402 CER)
FB2  Part_Number: 1000716  Resistance_at_Frequency: 120 @ 100MHz  [0603]  (hidden comment: PE-0603PFB121ST)
L1  Manufacturer_Part_Number1: MDWK4040T1R0MM  Part_Number: 1002223  Inductance: 1.0 uH  [MDWK4040]  (hidden comment: INDUCTOR)
L2  Manufacturer_Part_Number1: NRS3015T4R7MNGHV  Part_Number: 1002127  Inductance: 4.7 uH  [NRS3015]  (hidden comment: INDUCTOR)
R12  Resistance_Ohms: 300k  Part_Number: 1002126  [0402]  (hidden comment: RESISTOR)
R13  Part_Number: 1000796  Resistance_Ohms: 100k  [0402]  (hidden comment: R, 100K, 1%, 1/16W,  0402)
R14  Part_Number: 1000796  Resistance_Ohms: 100k  [0402]  (hidden comment: R, 100K, 1%, 1/16W,  0402)
R15  Part_Number: 1000797  Resistance_Ohms: 1M  [0402]  (hidden comment: R, 1M, 1%, 1/16W, 0402)
R16  Resistance_Ohms: 110K  Part_Number: 1002128  [0402]  (hidden comment: RESISTOR)
TP11  Test Point 1mm  [Test_Point 1mm]  (value not drawn)  (no BOM)
TP12  Test Point 1mm  [Test_Point 1mm]  (value not drawn)  (no BOM)
TP13  Test Point 1mm  [Test_Point 1mm]  (value not drawn)  (no BOM)
TP14  Test Point 1mm  [Test_Point 1mm]  (value not drawn)  (no BOM)
U6  Part_Number: 1001034  [PSON50P300X100_HS-11N]  (hidden comment: TPS61230DRCR)
U7  Manufacturer_Part_Number1: TLV61220DBVR  Part_Number: 1002116  [SOT95P280X110-6N]  (hidden comment: TLV61220)

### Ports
PWR_EN (in)

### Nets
GND: C12.2 C13.2 C14.2 C15.2 C16.2 C17.2 C19.2 C20.2 C21.2 C22.2 C23.2 R14.1 R16.1 U6.11(GNDPAD) U7.2(GND)
VCC_3V3: C12.1 C13.1 L1.1 R13.2 TP11.1 U6.10(VIN)
VCC_4V0: C14.1 C15.1 C16.1 C17.1 C18.2 C22.1 C23.1 L2.1 R12.2 TP12.1 U6.3(VOUT) U6.4(VOUT) U7.3(EN) U7.6(VBAT)
VCC_5V0: FB2.2
NetC18_1: C18.1 R12.1 R14.2 U6.7(FB)
NetC19_1: C19.1 U6.6(SS)
NetC20_1: C20.1 C21.1 FB2.1 R15.2 TP14.1 U7.5(VOUT)
NetL1_2: L1.2 U6.1(SW) U6.2(SW)
NetL2_2: L2.2 U7.1(SW)
NetR13_1: R13.1 TP13.1 U6.9(EN) ; port PWR_EN
NetR15_1: R15.1 R16.2 U7.4(FB)

Not connected (* = marked no-connect by the designer): U6 5(PG)* 8(HYS)*

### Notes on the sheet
- Power
- (near U6) DESIGN NOTE:
  Nominal Voltage on FB is 1.0V. VOUT set to 4.0V
- DESIGN NOTE:
  VOUT set to 5.04V
- © NimbeLink Corp. 2020. All rights reserved.

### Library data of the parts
C12 C14 C19 C20 C22 = 1000742: as C3 on sheet TOP
C13 C15-C17 = 1000932: Capacitor, 22 uF, 25V, 20%, X5R, 0603; Manufacturer1: TDK Corporation; Manufacturer_Part_Number1: C1608X5R1A226M080AC; Item_Phase: Production; Capacitor_Type: Ceramic; Mounting_Type: Surface Mount; Operating_Temperature: -55°C ~ 85°C; Thickness_Max: 0.035" (0.90mm); Voltage_Rating: 10V
C18 = 1000748: Capacitor, 18 pF, 50V, 5%, C0G/NPO, 0402; Manufacturer1: Samsung Electro-Mechanics America, Inc; Manufacturer_Part_Number1: CL05C180JB5NNNC; Item_Phase: Production; Capacitor_Type: Ceramic; Mounting_Type: Surface Mount; Operating_Temperature: -55°C ~ 125°C; Temperature_Coefficient: C0G, NP0; Thickness_Max: 0.022" (0.55mm)
C21 C23 = 1000737: Capacitor, 10 uF, 10V, 20%, X5R, 0402; Manufacturer1: Venkel LTD.; Manufacturer_Part_Number1: C0402X5R100-106MNP; Item_Phase: Production; Capacitor_Type: Ceramic; Mounting_Type: Surface Mount; Operating_Temperature: -55°C ~ 85°C; Thickness_Max: 0.035" (0.90mm)
FB2 = 1000716: as FB1 on sheet TOP
L1 = 1002223: Inductor, 1 uH, 5.1A, 20%, 27 mOhm, Shielded, 4.00x4.00x2.00mm; Manufacturer1: Taiyo Yuden; Item_Phase: Production; Current_Saturation: 7A; DC_Resistance: 27 mOhm; Mounting_Type: Surface Mount; Operating_Temperature: -40C to +125C; Inductor_Type: Wirewound
L2 = 1002127: Inductor, 4.7 uH, 1.04 A, 20%, 144 mOHM, Shielded, 3X3mm; Manufacturer1: Taiyo Yuden; Item_Phase: Production; Current_Saturation: 1.02A; Current_Rating: 1.04A; Mounting_Type: Surface Mount; Operating_Temperature: -40C to +125C; Inductor_Type: Wirewound
R12 = 1002126: Resistor, 300K, 1%, 1/16W, 0402; Manufacturer1: Stackpole Electronics Inc; Manufacturer_Part_Number1: RMCF0402FT300k; Item_Phase: Production; Mounting_Type: Surface Mount; Operating_Temperature: -55C to 155C; Resistor_Package: 0402 (1005 Metric); Temperature_Coefficient: ±100ppm/°C
R13 R14 = 1000796: Resistor, 100K, 1%, 1/16W, 0402; Manufacturer1: Bourns Inc; Manufacturer_Part_Number1: CR0402-FX-1003GLF; Item_Phase: Production; Mounting_Type: Surface Mount; Number_of_Terminations: 2; Operating_Temperature: -55°C ~ 155°C; Power: 0.063W, 1/16W; Resistor_Package: 0402 (1005 Metric); Temperature_Coefficient: ±100ppm/°C
R15 = 1000797: Resistor, 1M, 1%, 1/16W, 0402; Manufacturer1: Bourns Inc; Manufacturer_Part_Number1: CR0402-FX-1004GLF; Item_Phase: Production; Mounting_Type: Surface Mount; Number_of_Terminations: 2; Operating_Temperature: -55°C ~ 155°C; Power: 0.063W, 1/16W; Resistor_Package: 0402 (1005 Metric); Temperature_Coefficient: ±100ppm/°C
R16 = 1002128: Resistor, 110K, 1%, 1/16W, 0402; Manufacturer1: Yageo; Manufacturer_Part_Number1: RC0402FR-07110KL; Item_Phase: Production; Mounting_Type: Surface Mount; Operating_Temperature: -55C to +125C; Resistor_Package: 0402 (1005 Metric); Temperature_Coefficient: ±100ppm/°C
TP11-TP14 = TP_1mm: TEST POINT, SMD 1mm; Population: NP
U6 = 1001034: IC, Boost, ADJ, 2.5V-5.5V, 2.1A, VSON; Manufacturer1: Texas Instruments; Item_Phase: Production; Mounting_Type: Surface Mount; Operating_Temperature: -40°C ~ 125°C; Output_Type: Adjustable
U7 = 1002116: IC, BOOST, ADJ, 1.8V-5.5V, 0.22A, SOT-23-6; Manufacturer1: Texas Instruments; Item_Phase: Production; Mounting_Type: Surface Mount; Operating_Temperature: -40C to +85C; Voltage_Supply_Max: 5.5V; Voltage_Supply_Min: 0.7V; Voltage_Supply_Typical: 3.3

## Sheet ECO LIST.SchDoc: ECO LIST
size C; DocumentNumber: 6; SheetNumber: 6; SheetTotal: 6
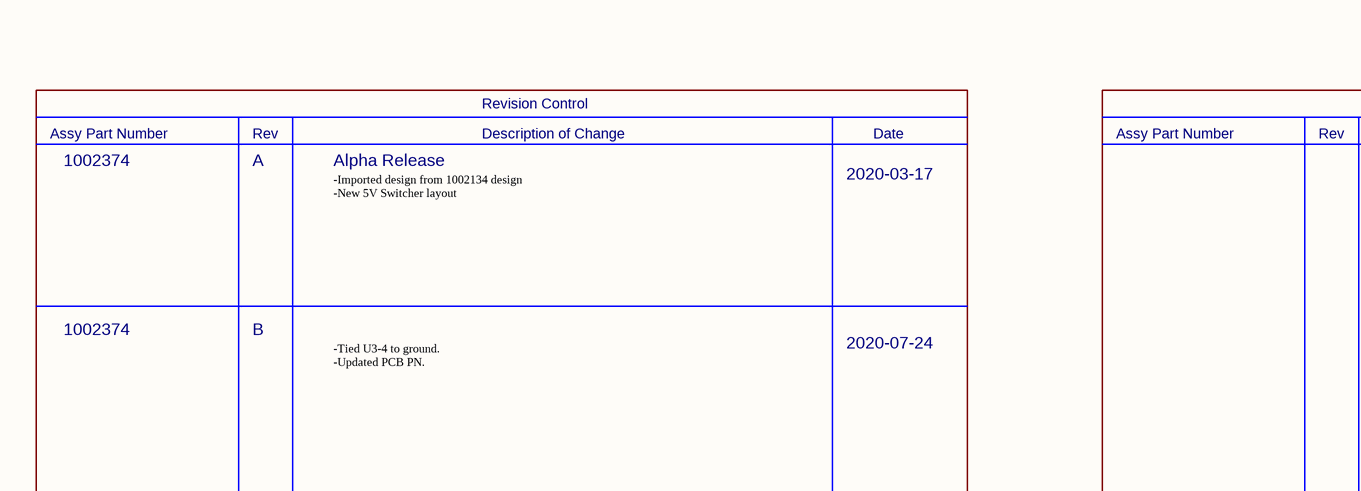
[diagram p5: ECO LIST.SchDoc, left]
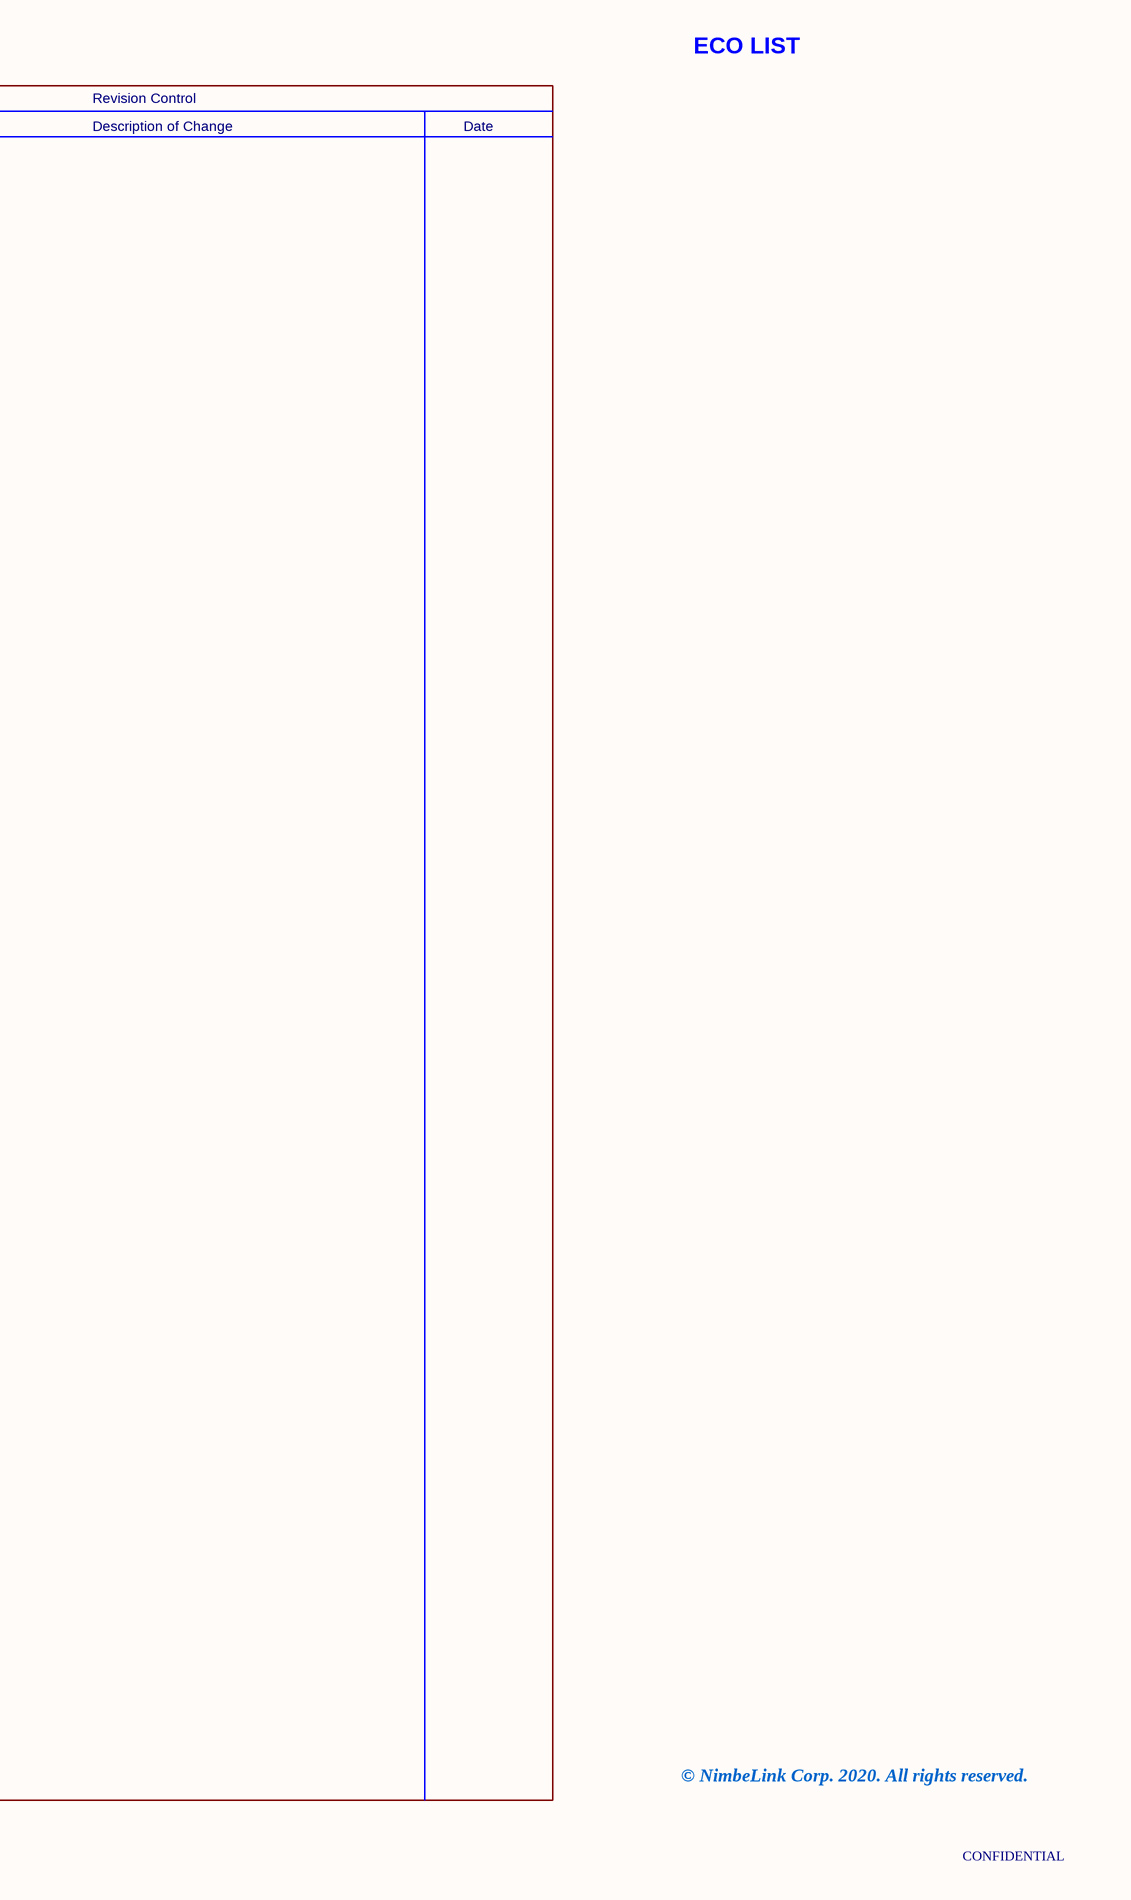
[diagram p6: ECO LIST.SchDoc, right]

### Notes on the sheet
- ECO LIST
- Assy Part Number
- Rev
- Description of Change
- Revision Control
- Date
- 1002374
- A
- Alpha Release
- 2020-03-17
- -Imported design from 1002134 design
  -New 5V Switcher layout
- B
- -Tied U3-4 to ground.
  -Updated PCB PN.
- 2020-07-24
- © NimbeLink Corp. 2020. All rights reserved.
- CONFIDENTIAL

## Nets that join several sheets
GND: TOP (38 pins), Power (15 pins)
VCC_3V3: TOP (11 pins), Power (6 pins)
VCC_4V0: TOP (8 pins), Power (14 pins)
VCC_5V0: TOP (R6.2), Power (FB2.2)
